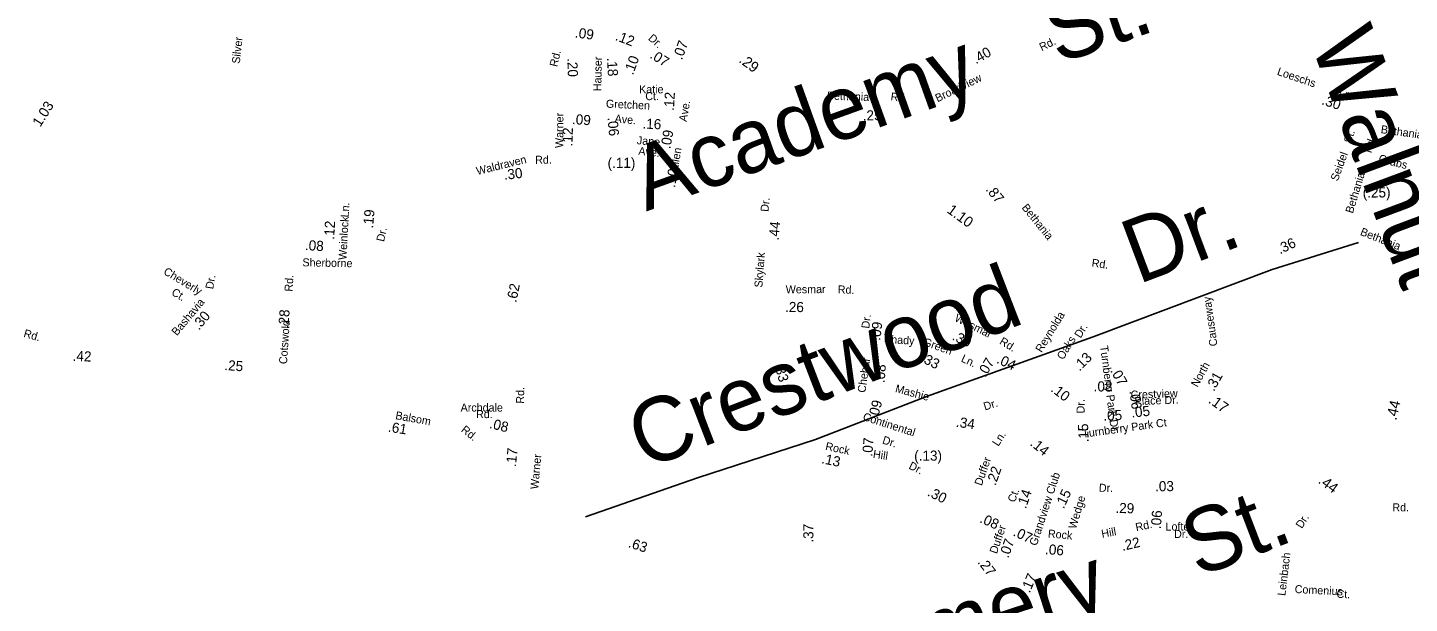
# Model space of a CAD drawing. Extents: x 1553981 to 1780076, y 812965 to 996873.
# Drawn here: x 1628079 to 1630129, y 851400 to 852253 of the extents above; entities that cross this region are included whole.
import ezdxf

# ---------------------------------------------------------------- set-up
doc = ezdxf.new("R2010")
doc.units = 0
for name, color, linetype in [('Exist Road Non-System Type 51 Label', 7, 'Continuous'), ('Exist Road Primary NC Service Mileage Hundredths English Label', 7, 'Continuous'), ('Exist Road Secondary Mileage Hundredths English Label', 7, 'Continuous'), ('Map Preparation Border Antique Large Shape', 7, 'Continuous')]:
    doc.layers.add(name, color=color, linetype=linetype)

msp = doc.modelspace()

# ---------------------------------------------------------------- linework, layer by layer
at = {"layer": 'Exist Road Non-System Type 51 Label'}
msp.add_lwpolyline([(1630053.2, 851934.3), (1629924.8, 851894.3), (1629659.4, 851794.5), (1629412.5, 851706.2), (1629247.7, 851642.7), (1629072.8, 851585.4), (1628906.2, 851528)], dxfattribs=at)

# ---------------------------------------------------------------- texts
for s, height, rotation, p in [('St.', 95, 18.9688, (1629607.1, 852198.6)), ('Walnut', 95, 290.3961, (1629981.3, 852231.3)), ('Silver', 11.88, 83.7443, (1628393.5, 852199.1)), ('Academy', 95, 19.7956, (1628996.2, 851980.3)), ('St.', 11.88, 71.9338, (1630042, 852080.8)), ('Seidel', 11.88, 69.8531, (1630022.3, 852024.7)), ('Grabs', 11.88, 345.7251, (1630081.9, 852053.9)), ('Dr.', 95, 20.6246, (1629725.9, 851872.1)), ('Cheverly', 11.88, 329.0172, (1628279.4, 851888.4)), ('Crestwood', 95, 21.0737, (1628993.6, 851597.5)), ('Ct.', 11.88, 329.0172, (1628291.2, 851857.6)), ('Reynolda', 11.87, 58.5004, (1629583, 851770.4)), ('Dr.', 11.87, 58.5004, (1629640.8, 851791.9)), ('Oaks', 11.87, 58.5004, (1629614.9, 851759.7)), ('St.', 95, 20.9602, (1629814.6, 851437.7)), ('Dr.', 11.88, 58.0623, (1629969.1, 851509.6)), ('Montgomery', 95, 18.0666, (1629015.7, 851176.2)), ('Leinbach', 11.88, 83.2298, (1629944.5, 851410.2))]:
    msp.add_text(s, height=height, rotation=rotation, dxfattribs=at).set_placement(p)
at = {"layer": 'Exist Road Primary NC Service Mileage Hundredths English Label'}
for s, rotation, p in [('.29', 323.3101, (1629132.9, 852202.7)), ('1.10', 323.8309, (1629441.5, 851979.8)), ('.17', 324.5058, (1629829.3, 851697.8)), ('.44', 323.5664, (1629992.2, 851578.9))]:
    msp.add_text(s, height=15.62, rotation=rotation, dxfattribs=at).set_placement(p)
at = {"layer": 'Exist Road Secondary Mileage Hundredths English Label'}
for s, height, rotation, p in [('.09', 15, 352.5639, (1628890.1, 852238.6)), ('.12', 15, 338.951, (1628949.5, 852235)), ('.07', 15, 69.7205, (1629049.5, 852204.3)), ('.40', 15, 29.5842, (1629485.6, 852198.6)), ('.20', 15, 272.1199, (1628879.4, 852207.6)), ('.18', 15, 273.3498, (1628938.2, 852208.3)), ('.10', 15, 70.1761, (1628976.9, 852181.9)), ('.07', 15, 327.6881, (1629000.7, 852209)), ('1.03', 15, 57.7364, (1628097.6, 852104.9)), ('.12', 15, 86.501, (1629037.5, 852129.4)), ('.30', 15, 341.7776, (1629997.4, 852139.6)), ('.09', 15, 356.0001, (1628886, 852110.2)), ('.06', 15, 274.6395, (1628939.2, 852119.6)), ('.16', 15, 357.4491, (1628990.7, 852103.5)), ('.25', 15, 1.7919, (1629317.9, 852115.2)), ('.12', 15, 88.2887, (1628887, 852076.9)), ('.09', 15, 80.3117, (1629032.3, 852072.6)), ('(.11)', 15, 0.5014, (1628939.2, 852044.9)), ('.30', 15, 6.7109, (1628786, 852027.3)), ('.10', 15, 79.3427, (1629039, 852015.1)), ('.87', 15, 309.6137, (1629499.3, 852012.6)), ('(.25)', 15, 0.4042, (1630059.4, 852001.1)), ('.19', 15, 84.8892, (1628591.2, 851955.1)), ('.12', 15, 86.7556, (1628533.5, 851938.5)), ('.44', 15, 85.1398, (1629193, 851937.4)), ('.08', 15, 356.4437, (1628489.9, 851923.4)), ('.36', 15, 25.4128, (1629936.6, 851916.9)), ('.62', 15, 78.4548, (1628803.7, 851844.8)), ('.30', 15, 50.0425, (1628333, 851803.7)), ('.28', 15, 85.711, (1628465.6, 851806.9)), ('.26', 15, 359.516, (1629202.4, 851831.5)), ('.09', 15, 82.8623, (1629343.5, 851788.4)), ('.30', 15, 333.7243, (1629449.2, 851790.9)), ('.42', 15, 357.2985, (1628145.4, 851759.2)), ('.13', 15, 45.2897, (1629639.3, 851742.9)), ('.25', 15, 355.8524, (1628370.3, 851745.5)), ('.33', 15, 285.9521, (1629186.3, 851753.1)), ('.08', 15, 85.8632, (1629350.1, 851725.7)), ('.33', 15, 333.1757, (1629402, 851758.8)), ('.07', 15, 59.6524, (1629499.6, 851733.6)), ('.04', 15, 334.7088, (1629515.2, 851756.4)), ('.08', 15, 359.0791, (1629660.1, 851713.9)), ('.07', 15, 299.5903, (1629684.3, 851744.6)), ('.31', 15, 60.8742, (1629838.6, 851712.9)), ('.10', 15, 322.8034, (1629595.5, 851714.8)), ('.06', 15, 277.7811, (1629713.2, 851714.2)), ('.09', 15, 75.24, (1629339.8, 851671.7)), ('.05', 15, 5.8512, (1629716.7, 851674.9)), ('.44', 15.62, 77.0054, (1630109, 851670.2)), ('.61', 15, 351.055, (1628612.8, 851654.2)), ('.08', 15, 345.9301, (1628763, 851659.7)), ('.34', 15, 351.9287, (1629455.3, 851661.5)), ('.05', 15, 2.6312, (1629674.9, 851670.2)), ('.15', 15, 92.4309, (1629653, 851638.5)), ('.17', 15, 84.7962, (1628803.2, 851601.5)), ('.07', 15, 85.3471, (1629331.7, 851616.8)), ('(.13)', 15, 359.9717, (1629394, 851611.1)), ('.14', 15, 320.651, (1629564.8, 851634.8)), ('.13', 15, 348.2221, (1629255.6, 851607.4)), ('.22', 15, 70.7283, (1629514.6, 851573.2)), ('.30', 15, 333.5077, (1629412.5, 851559.7)), ('.14', 15, 70.9154, (1629559.6, 851538.9)), ('.15', 15, 64.8314, (1629615.7, 851538.9)), ('.03', 15, 0.6719, (1629751.4, 851565.6)), ('.29', 15, 358.5494, (1629692.4, 851533.6)), ('.08', 15, 336.3311, (1629490.1, 851520)), ('.06', 15, 86.0241, (1629759.9, 851509.2)), ('.37', 15, 89.5177, (1629244.4, 851489.5)), ('.07', 15, 334.4013, (1629539.6, 851500.4)), ('.63', 15, 341.9659, (1628968.8, 851483.2)), ('.07', 15, 70.6507, (1629533.7, 851465.7)), ('.06', 15, 355.6555, (1629587.7, 851472.6)), ('.22', 15, 13.1029, (1629703.1, 851477.2)), ('.27', 15, 307.9246, (1629487.3, 851460.3)), ('.17', 15, 66.849, (1629565.3, 851414))]:
    msp.add_text(s, height=height, rotation=rotation, dxfattribs=at).set_placement(p)
at = {"layer": 'Map Preparation Border Antique Large Shape'}
for s, height, rotation, p in [('Dr.', 11.88, 318.3735, (1628998.6, 852236)), ('Rd.', 11.87, 26.1821, (1629583.2, 852218)), ('Rd.', 11.88, 76.4902, (1628864.4, 852194.2)), ('Hauser', 11.88, 88.9496, (1628929.8, 852158.7)), ('Broadview', 11.88, 25.8989, (1629428.7, 852142.3)), ('Loeschs', 11.88, 341.2924, (1629931.4, 852183.3)), ('Bethania', 11.88, 357.8621, (1629264.3, 852146.5)), ('Ln.', 11.88, 341.7776, (1630022.9, 852152.5)), ('Gretchen', 11.88, 357.4491, (1628936.5, 852134.5)), ('Ave.', 11.88, 79.9701, (1629056.4, 852113)), ('Rd.', 11.87, 352.1944, (1629358.5, 852145.4)), ('Warner', 11.88, 89.4983, (1628873.3, 852074.6)), ('Ave.', 11.87, 355.1269, (1628949.3, 852112.5)), ('Bethania - Rural Hall', 11.875, 352.0432, (1630085.6, 852096.8)), ('Jane', 11.88, 355.5315, (1628982.3, 852080.3)), ('Rd.', 11.88, 72.64, (1630072.1, 852066.3)), ('Waldraven', 11.88, 13.7751, (1628746, 852034.5)), ('Rd.', 11.88, 1.0874, (1628831.8, 852051.1)), ('Ave.', 11.88, 354.0154, (1628984.4, 852064.6)), ('Ellen', 11.87, 80.0098, (1629043, 852039.5)), ('Bethania', 11.87, 73.0992, (1630044.6, 851976.9)), ('Dr.', 11.88, 84.4039, (1629177.7, 851979.6)), ('Ln.', 11.88, 86.7556, (1628555, 851971.5)), ('Bethania', 11.88, 309.0265, (1629552.8, 851985.9)), ('Weinlock', 11.88, 86.7556, (1628551.7, 851908.4)), ('Dr.', 11.88, 77.3812, (1628607.5, 851935)), ('Bethania', 11.88, 338.1952, (1630054.6, 851946)), ('Skylark', 11.87, 85.7184, (1629168.7, 851867.4)), ('Sherborne', 11.87, 358.9296, (1628486.5, 851899.2)), ('Rd.', 11.87, 352.1944, (1629656.7, 851898.8)), ('Dr.', 11.87, 80.1672, (1628354.1, 851864.7)), ('Rd.', 11.87, 86.2358, (1628471.7, 851861.4)), ('Wesmar', 11.88, 0.5033, (1629203.5, 851859)), ('Rd.', 11.88, 358.1991, (1629280.5, 851859.1)), ('Causeway', 11.88, 97.9942, (1629844, 851781.5)), ('Bashavia', 11.88, 50.0425, (1628300.3, 851795.5)), ('Cotswold', 11.87, 86.2358, (1628463.6, 851753.9)), ('Dr.', 11.88, 82.8623, (1629327.3, 851806.4)), ('Wesmar', 11.88, 333.7243, (1629452.8, 851818.6)), ('Rd.', 11.88, 344.2082, (1628072.1, 851794.8)), ('Shady', 11.88, 356.6171, (1629349.1, 851785.6)), ('Green', 11.88, 340.4017, (1629406.4, 851782.5)), ('Rd.', 11.88, 328.6042, (1629519.5, 851784.9)), ('Turnberry Park Dr', 11.875, 277.2557, (1629669.7, 851780.9)), ('Chebar', 11.87, 82.1655, (1629321.6, 851711.3)), ('Ln.', 11.88, 334.6669, (1629462.5, 851758.5)), ('North', 11.88, 61.0417, (1629814.2, 851719.1)), ('Rd.', 11.88, 89.5077, (1628815.3, 851695.5)), ('Mashie', 11.88, 344.9889, (1629365, 851712.9)), ('Crestview', 11.88, 1.9406, (1629715.3, 851702.9)), ('Dr.', 11.88, 17.1375, (1629498.9, 851685.4)), ('Dr.', 11.88, 90.133, (1629646.7, 851681.2)), ('Place Dr.', 11.88, 1.9406, (1629721.2, 851693.4)), ('Balsom', 11.88, 349.6165, (1628623.8, 851672.8)), ('Continental', 11.875, 342.1879, (1629316.9, 851671.5)), ('Turnberry Park Ct', 11.875, 7.8504, (1629644.2, 851645)), ('Rd.', 11.88, 321.7388, (1628720.9, 851655)), ('Dr.', 11.88, 342.1879, (1629345.8, 851636.8)), ('Ln.', 11.87, 57.3193, (1629518.8, 851631.5)), ('Rock', 11.88, 347.8552, (1629261.5, 851627.2)), ('Hill', 11.88, 351.731, (1629332.3, 851615.3)), ('Warner', 11.88, 84.7962, (1628836.3, 851568.3)), ('Dr.', 11.88, 333.2262, (1629384.8, 851599.7)), ('Duffer', 11.88, 70.7283, (1629494.1, 851573.1)), ('Grandview Club', 11.875, 71.9652, (1629575.7, 851484)), ('Ct.', 11.87, 69.4606, (1629543.2, 851548.3)), ('Dr.', 11.87, 358.7608, (1629667.9, 851565.1)), ('Wedge', 11.88, 73.5655, (1629633.9, 851508.9)), ('Duffer', 11.87, 70.9154, (1629516.5, 851472.2)), ('Rock', 11.88, 354.9237, (1629592, 851497.3)), ('Hill', 11.88, 10.5453, (1629672.8, 851496.6)), ('Rd.', 11.88, 12.2074, (1629723.6, 851506.4)), ('Comenius', 11.88, 357.0917, (1629958.2, 851414.9)), ('Ct.', 11.88, 358.0279, (1630020.3, 851407.8))]:
    msp.add_text(s, height=height, rotation=rotation, dxfattribs=at).set_placement(p)
for s, p in [('Katie', (1628985.9, 852155.8)), ('Ct.', (1628995.1, 852145.6)), ('Archdale', (1628721.2, 851683.9)), ('Rd.', (1628744.1, 851674.2)), ('Rd.', (1630103.3, 851535.9)), ('Lofter', (1629766.8, 851507.5)), ('Dr.', (1629779.5, 851496.5))]:
    msp.add_text(s, height=11.88, dxfattribs=at).set_placement(p)

doc.saveas('drawing.dxf')
